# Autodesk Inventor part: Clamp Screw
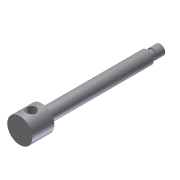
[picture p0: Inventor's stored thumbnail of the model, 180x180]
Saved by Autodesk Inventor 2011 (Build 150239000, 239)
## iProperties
Shininess: 77.0
Length Units: 11269
Angle Units: 11279
Time Units: 11290
Mass Units: 11283
Length Display Precision: 3
Angle Display Precision: 2
Created: 2002-02
Part Number: Clamp Screw
Document SubType Name: Modeling
Designer: ***
Density: 1 g/cm^3
Density: 0.0
Volumn: 0.0
Area: 0.0
PropertySet Name: Model Information
Control State: 0
Master: False
Checked Out: False
Author: ***
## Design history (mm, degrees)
sketch "Sketch1"
  geometry: L1 (0, 140)-(5, 140); L2 (5, 140)-(5, 132); L3 (5, 132)-(4, 132); L4 (4, 132)-(4, 127); L5 (4, 127)-(6.5, 127); L6 (6.5, 127)-(6.5, 25); L7 (6.5, 25)-(4, 25); L8 (4, 25)-(4, 22); L9 (4, 22)-(12.5, 22); L10 (12.5, 22)-(12.5, 0); L11 (12.5, 0)-(0, 0); L12 (0, 0)-(0, 140)
  constraints: 24 end point, 10 parallel, 1 horizontal, 1 perpendicular
  dimensions: "d0" = 10 diameter of L2 L12; "d1" = 8 diameter of L4 L12; "d2" = 13 diameter of L6 L12; "d3" = 8 diameter of L7.end L12; "d4" = 25 diameter of L10 L12; "d5" = 3 distance from line of L7.end L9; "d6" = 8 distance of L1.end L2.end; "d7" = 13 vertical distance of L1.end L5.end; "d8" = 22 distance of L9.end L10.end; "d10" = 102 distance of L5.end L6.end
revolve "Revolution1" sketch "Sketch1" stored, may be unused: angle "d11" = 90 deg
sketch "Sketch3"
  geometry: L1 (-12.5, 0)-(12.5, 0) reference; C1 r 5 at (-0.113, 11)
  constraints: 1 centre point
  dimensions: "d13" = 10 diameter of C1; "d14" = 11 distance from line of L1 C1.centre
extrude "Extrusion1" cut sketch "Sketch3" stored distance "d15" = 10; taper "d16" = 0 deg
body "Solid1"
